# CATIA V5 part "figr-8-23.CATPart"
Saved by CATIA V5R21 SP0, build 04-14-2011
Part number: Part1
Bounding box of the stored display mesh (mm): x -50 to 50, y -62.5 to 62.5, z 0 to 10
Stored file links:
  D:\CATIA V5R21 E-RESOURCES\CATIA-V5R21\catia-v5r21-prt\c08-catia-v5r20-prt\c08-catia-v5r21-figr-8-23.CATPart
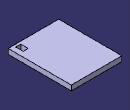
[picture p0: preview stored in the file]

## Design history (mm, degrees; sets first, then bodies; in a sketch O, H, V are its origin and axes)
Body1 (main body)
  Sketch1 on xy-plane, origin (0, 0, 0), H (1, 0, 0), V (0, 1, 0)
    line L1 (-50, 62.5) -> (50, 62.5)
    line L2 (50, 62.5) -> (50, -62.5)
    line L3 (50, -62.5) -> (-50, -62.5)
    line L4 (-50, -62.5) -> (-50, 62.5)
    axis line L5 (50, -62.5) -> (-50, 62.5)
    length L3 = 100
    length L2 = 125
    horizontal: L1 H, L3 H
    vertical: L2 V, L4 V
    midpoint: O L5
  Pad1: profile Sketch1, direction (0, 0, 1), length 10
  Sketch2 on face of Pad1, origin (0, 0, 10), H (1, 0, 0), V (0, 1, 0)
    line L1 (40, -57.5) -> (30, -57.5)
    line L2 (30, -57.5) -> (30, -42.5)
    line L3 (30, -42.5) -> (40, -42.5)
    line L4 (40, -42.5) -> (40, -57.5)
    reference projected line E1 (-50, -62.5) -> (50, -62.5) from edge [face of Pad1 | face of Pad1]
    reference projected line E2 (50, -62.5) -> (50, 62.5) from edge [face of Pad1 | face of Pad1]
    length L1 = 10
    length L4 = 15
    distance L1 E1 = 5
    distance L4 E2 = 10
    horizontal: L1 H, L3 H
    vertical: L2 V, L4 V
  Pocket1: profile Sketch2, direction (0, 0, -1), through (limit type 3)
